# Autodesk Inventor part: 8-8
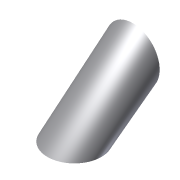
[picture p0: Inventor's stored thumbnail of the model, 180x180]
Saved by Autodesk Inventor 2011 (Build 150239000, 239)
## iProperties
Created: 2014-01
Part Number: 8-8
Document SubType Name: Modeling
Designer: Administrator
Density: 1 g/cm^3
Author: Administrator
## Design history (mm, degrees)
sketch "草图1"
  geometry: C1 r 18 at (0, 0); 1 further point
  constraints: 1 centre point, 1 coincident
  dimensions: "d0" = 36 diameter of C1
node "工作平面1"
sketch "草图2"
  geometry: L1 (0, 0)-(0, 31); C1 r 18 at (0, 31)
  constraints: 2 end point, 1 centre point, 1 coincident, 1 vertical
  dimensions: "d2" = 31 distance of L1.start L1.end; "d3" = 36 diameter of C1
feature "放样1" sketch "草图2" dims "d4" = 0, "d5" = 90 deg, "d6" = 0, "d7" = 90 deg
node "实体1"
other parameters: "d1" = 39
